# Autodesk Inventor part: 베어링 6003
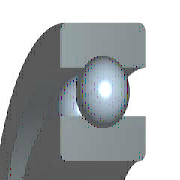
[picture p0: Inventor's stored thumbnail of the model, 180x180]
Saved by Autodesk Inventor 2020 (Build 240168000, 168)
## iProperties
Created: 2012-02
Part Number: 베어링 6003
Material: 강철, 연강
Description: 깊은 그루브 볼 베어링
Document SubType Name: Modeling
Standard: KS B 2023
Designer: mduedu
Standards Organization: KS
Language: ko-KR
Size Designation: 6003 - 17 x 35 x 10
Categories: <MemberInstance><Categories><Category DisplayName="샤프트 부품" InternalName="7f7aeb1f-a693-4053-b835-cee3144e0d98" Mnemonic="SHFT"><Category DisplayName="베어링" Inter
Density: 7.86 g/cm^3
Mass: 39.0276 g
Surface Area: 48.7538 cm^2
Volume: 4.96535 cm^3
Appearance: 노란색
IsCustomPart: 1
Author: mduedu
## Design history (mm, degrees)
sketch "스케치" dims "d0" = 4.68 (= -0.26 x WD + 0.26 x BD)
  geometry: L1 (2.66, 13)-(7.34, 13); L2 (5, 13)-(5, 10.66); L3 (5, 13)-(5, 15.34); L4 (3.261, 11.434)-(0, 11.434); L5 (0, 8.5)-(10, 8.5); L6 (3.261, 14.566)-(0, 14.566); L7 (0, 17.5)-(10, 17.5); L8 (10, 8.5)-(10, 11.434); L9 (6.739, 11.434)-(10, 11.434); L10 (6.739, 14.566)-(10, 14.566); L11 (10, 17.5)-(10, 14.566); L12 (-1.4, 0)-(8.4, 0) reference; L13 (0, -0.3)-(0, 5.3) reference
  constraints: 22 end point, 4 point on line, 2 collinear, 2 perpendicular, 2 symmetric about line, 1 midpoint, 1 parallel, 14 other
  dimensions: "d9" = 17 diameter of L5 L12 (= WD); "d11" = 35 diameter of L7 L12 (= BD); "d12" = 10 distance between parallel lines of L8 L13 (= KB); "d13" = 22.868 diameter of L9 L12 (= 0.326 x BD + 0.674 x WD)
revolve "본체" stored, may be unused: angle "d6" = 90 deg
revolve "볼" stored, may be unused: angle "d7" = 90 deg
pattern_circular "IDS_ARRAYBALL[SIMPL:T]" dims angle "d3" = 360 deg
body "Solid1"
fillet "모깎기1" dims "d1" = 0.3 (= KRS)
other parameters: "WD" = 17 [user parameter; used in 5 equation terms], "BD" = 35 [user parameter; used in 5 equation terms], "KB" = 10 [user parameter; used in 1 equation term], "KRS" = 0.3 [user parameter; used in 1 equation term], "d4" = 0, "d5" = 0, "d8" = 0, "d14" = 0, "d15" = 0, "BBA" = 0 [user parameter], "BC0" = 3250000 [user parameter], "BC" = 6050000 [user parameter], "BR" = 17.5 (= 0.5 x BD) [user parameter], "WR" = 8.5 (= 0.5 x WD) [user parameter]
